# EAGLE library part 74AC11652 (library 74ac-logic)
Octal BUS TRANSCEIVER/REGISTER, 3-state
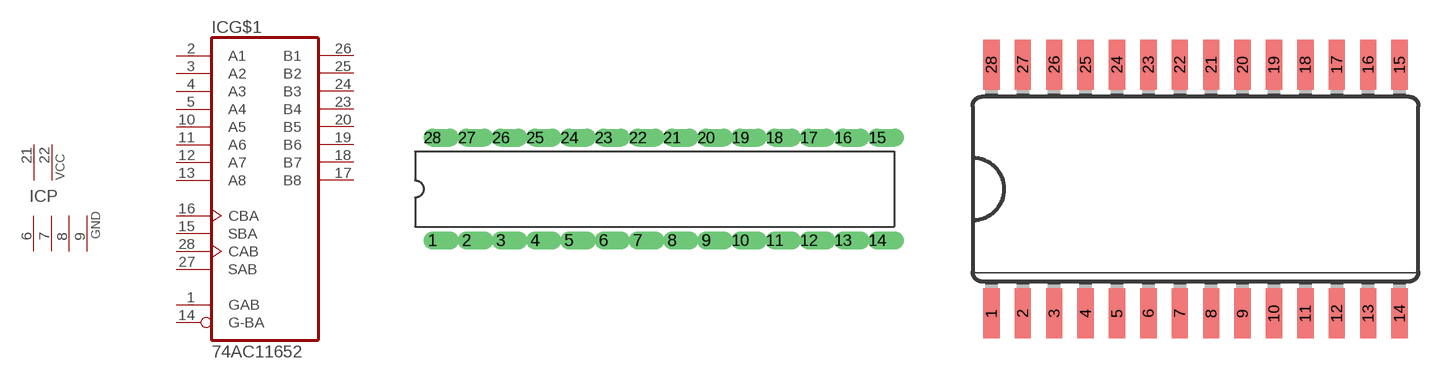
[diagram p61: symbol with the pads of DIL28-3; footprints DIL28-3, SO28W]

Designator prefix IC; gates G$1=7411652 P=2PWR4GND

## 74AC11652  [DIL28-3]
1  G$1:GAB  in
2  G$1:A1
3  G$1:A2
4  G$1:A3
5  G$1:A4
6  P:GND  pwr
7  P:GND  pwr
8  P:GND  pwr
9  P:GND  pwr
10  G$1:A5
11  G$1:A6
12  G$1:A7
13  G$1:A8
14  G$1:G-BA  in
15  G$1:SBA  in
16  G$1:CBA  in
17  G$1:B8
18  G$1:B7
19  G$1:B6
20  G$1:B5
21  P:VCC  pwr
22  P:VCC  pwr
23  G$1:B4
24  G$1:B3
25  G$1:B2
26  G$1:B1
27  G$1:SAB  in
28  G$1:CAB  in

## 74AC11652D  [SO28W]
Pads as for DIL28-3

## Footprint DIL28-3 (pad centres in mm)
Dual In Line 0.3 inch
drill 0.813 offset: 1 -16.51,-3.81; 2 -13.97,-3.81; 3 -11.43,-3.81; 4 -8.89,-3.81; 5 -6.35,-3.81; 6 -3.81,-3.81; 7 -1.27,-3.81; 8 1.27,-3.81; 9 3.81,-3.81; 10 6.35,-3.81; 11 8.89,-3.81; 12 11.43,-3.81; 13 13.97,-3.81; 14 16.51,-3.81; 15 16.51,3.81; 16 13.97,3.81; 17 11.43,3.81; 18 8.89,3.81; 19 6.35,3.81; 20 3.81,3.81; 21 1.27,3.81; 22 -1.27,3.81; 23 -3.81,3.81; 24 -6.35,3.81; 25 -8.89,3.81; 26 -11.43,3.81; 27 -13.97,3.81; 28 -16.51,3.81

## Footprint SO28W (pad centres in mm)
Wide Small Outline package 300 mil
smd 0.66 x 2.032: 1 -8.255,-5.029; 2 -6.985,-5.029; 3 -5.715,-5.029; 4 -4.445,-5.029; 5 -3.175,-5.029; 6 -1.905,-5.029; 7 -0.635,-5.029; 8 0.635,-5.029; 9 1.905,-5.029; 10 3.175,-5.029; 11 4.445,-5.029; 12 5.715,-5.029; 13 6.985,-5.029; 14 8.255,-5.029; 15 8.255,5.029; 16 6.985,5.029; 17 5.715,5.029; 18 4.445,5.029; 19 3.175,5.029; 20 1.905,5.029; 21 0.635,5.029; 22 -0.635,5.029; 23 -1.905,5.029; 24 -3.175,5.029; 25 -4.445,5.029; 26 -5.715,5.029; 27 -6.985,5.029; 28 -8.255,5.029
